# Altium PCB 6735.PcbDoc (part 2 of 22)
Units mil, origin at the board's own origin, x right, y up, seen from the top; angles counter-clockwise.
Board outline 2641.73 x 5165.35 mil, 6 copper layers (Top, Inner Layer 2, Inner Layer 3, Inner Layer 4, Inner Layer 5, Bottom), stack 35.7 mil thick; 1011 components, 790 nets, 4118 pads, 9325 vias.
Unrouted connection lines stored in the file: 4610.
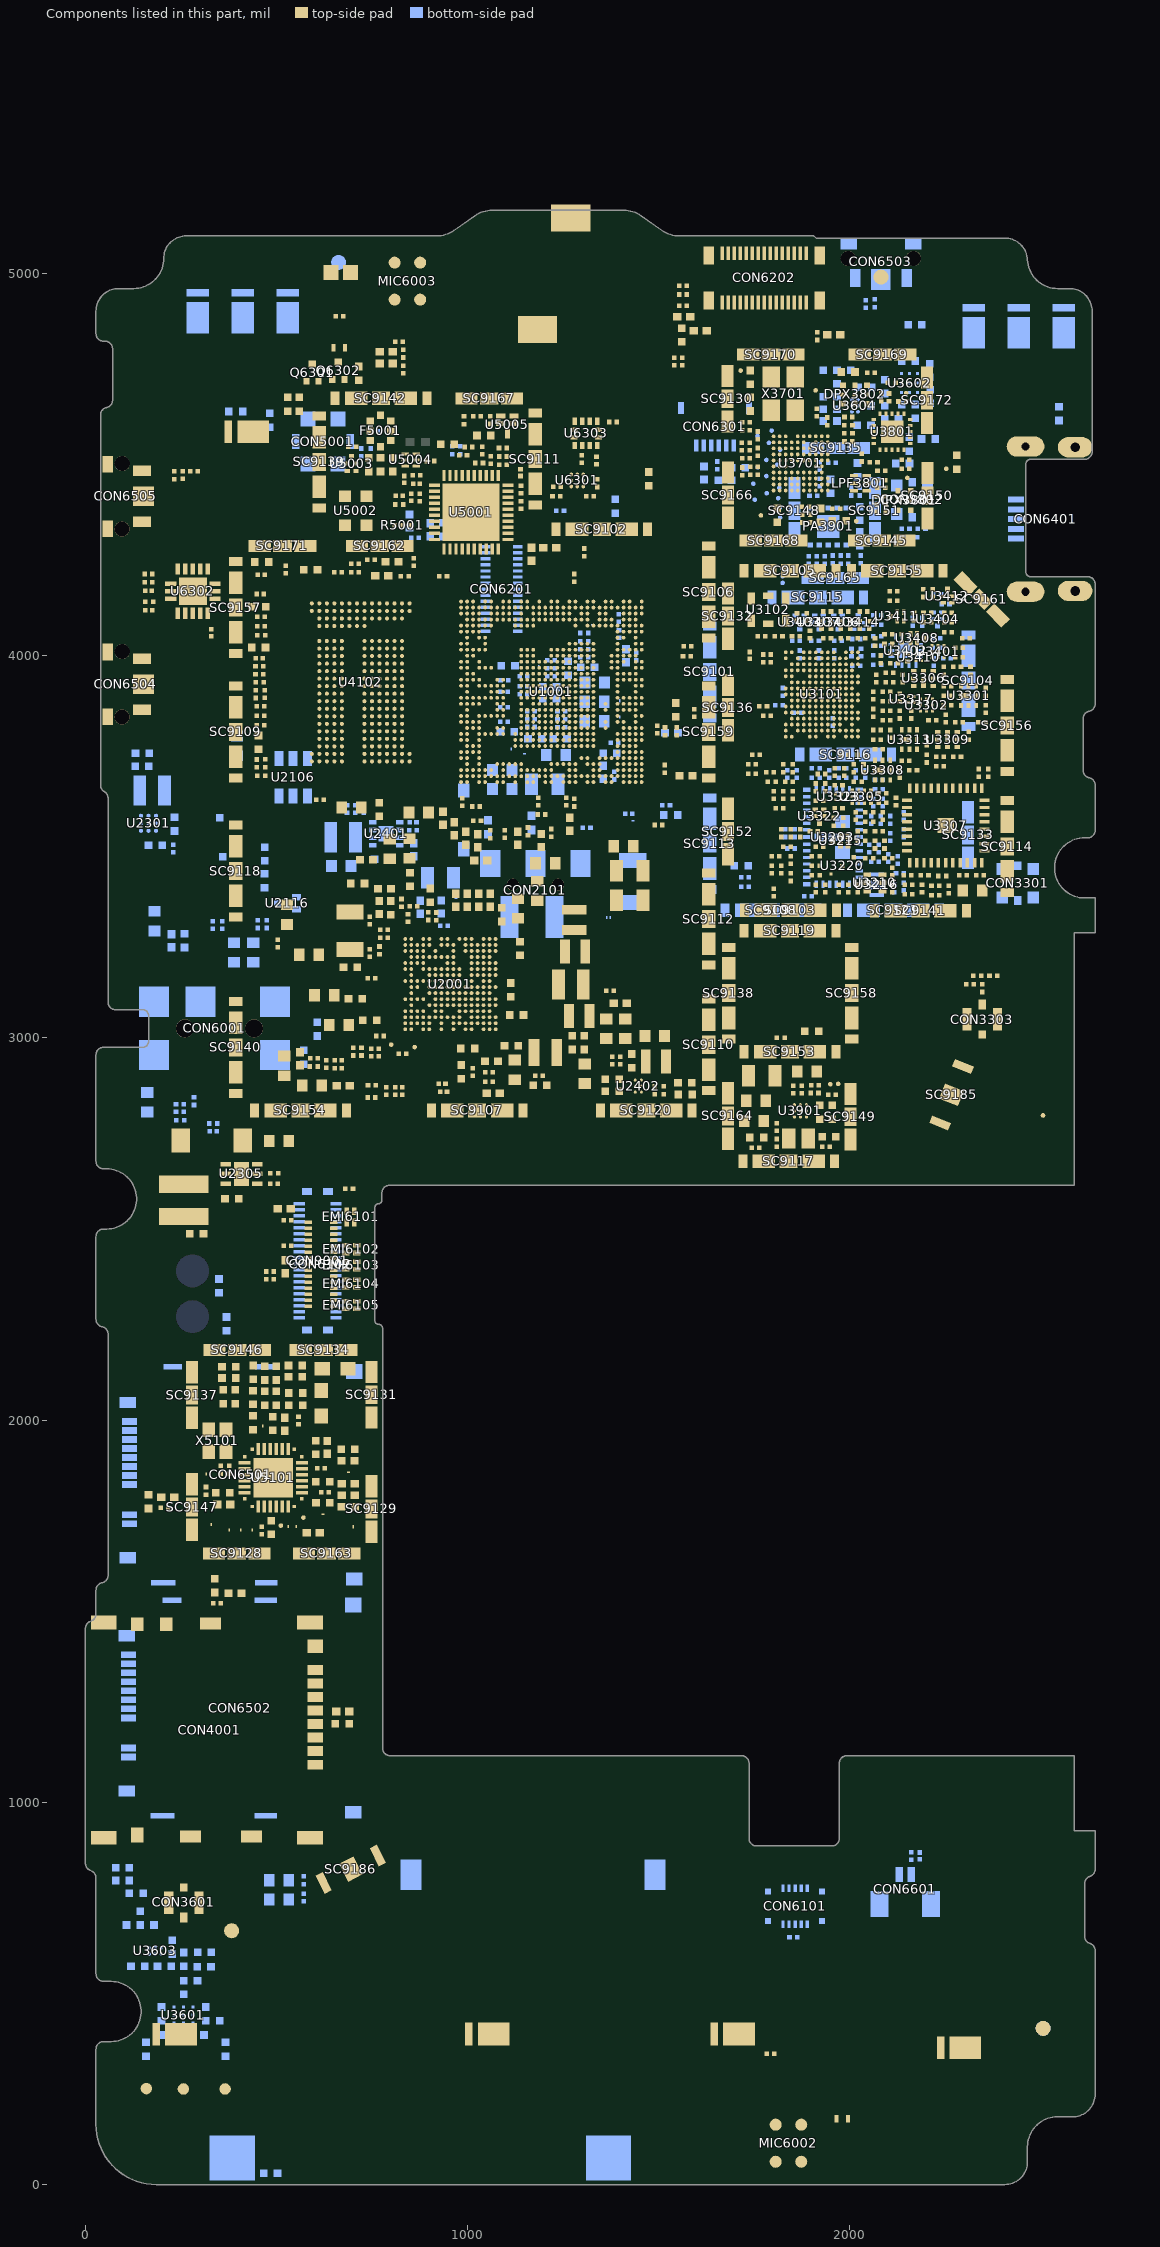
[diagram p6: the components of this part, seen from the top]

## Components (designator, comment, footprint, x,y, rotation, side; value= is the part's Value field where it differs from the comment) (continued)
C3914 "C0402" C0402 1921.08,2805.58 r90 top
C3915 "C0201" C0201 1937.31,2715.56 r0 top
C3916 "C0201" C0201 1909.08,2876.58 r0 top
C4001 "C0402" C0402 671.95,1205.49 r0 top
C4101 "C0402" C0402 452.95,4021.49 r180 top
C4102 "C0201" C0201 459.95,4053.49 r180 top
C4103 "C0402" C0402 589.08,4225.33 r180 top
C4104 "C0402" C0402 768.95,3597.49 r90 top
C4105 "C0201" C0201 660.72,4218.66 r0 top
C4106 "C0201" C0201 613.95,3623.49 r0 top
C4107 "C0201" C0201 458.95,4077.49 r180 top
C4108 "C0201" C0201 455.95,3930.49 r180 top
C4109 "C0201" C0201 704.95,4240.49 r180 top
C4110 "C0201" C0201 704.95,4218.49 r180 top
C4111 "C0402" C0402 453.31,4128.09 r180 top
C4112 "C0201" C0201 458.95,4101.49 r180 top
C4113 "C0402" C0402 461.31,4245.09 r180 top
C4114 "C0201" C0201 523.95,4225.49 r90 top
C4115 "C0201" C0201 468.95,3899.49 r90 top
C4116 "C0201" C0201 445.31,3899.39 r90 top
C5001 "C0201" C0201 820.95,4395.49 r180 top
C5002 "C0201" C0201 1139.45,4393.99 r90 top
C5003 "C0402" C0402 393.31,4639.09 r180 bottom
C5004 "C0201" C0201 698.08,4547.11 r180 top
C5005 "C0201" C0201 1139.45,4434.99 r270 top
C5006 "C0402" C0402 1042.31,4576.09 r0 top
C5007 "C0201" C0201 1060.08,4512.11 r270 top
C5008 "C0201" C0201 988.31,4524.09 r0 top
C5009 "C0201" C0201 874.08,4414.11 r90 top
C5011 "C0402" C0402 741.08,4500.11 r90 top
C5012 "C0201" C0201 866.08,4472.11 r0 top
C5013 "C0201" C0201 961.45,4317.99 r270 bottom
C5014 "C0201" C0201 971.95,4350.49 r0 bottom
C5015 "C0201" C0201 746.95,4250.83 r0 top
C5016 "C0201" C0201 1092.08,4521.11 r180 top
C5017 "C0402" C0402 804.08,4500.11 r270 top
C5101 "C0402" C0402 375.31,2110.09 r180 top
C5102 "C0402" C0402 375.31,2140.09 r180 top
C5104 "C0402" C0402 499.31,2057.09 r90 top
C5105 "C0402" C0402 469.31,2123.09 r90 top
C5106 "C0402" C0402 469.31,2057.09 r90 top
C5107 "C0402" C0402 499.31,2123.09 r90 top
C5108 "C0402" C0402 550.31,2039.09 r0 top
C5109 "C0402" C0402 549.31,2143.09 r0 top
C5110 "C0402" C0402 360.31,2061.09 r270 top
C5111 "C0402" C0402 550.31,2071.09 r180 top
C5112 "C0402" C0402 549.31,2113.09 r0 top
C5115 "C0402" C0402 490.31,1991.09 r270 top
C5116 "C0201" C0201 557.31,1999.09 r270 top
C5117 "C0402" C0402 438.31,1993.09 r270 top
C5119 "C0402" C0402 359.31,1810.09 r0 top
C5120 "C0201" C0201 315.31,1815.09 r90 top
C5121 "C0201" C0201 460.95,1711.49 r90 top
C5122 "C0402" C0402 621.3,1784.09 r0 top
C5123 "C0201" C0201 616.3,1874.09 r0 top
C5124 "C0402" C0402 602.95,1928.49 r90 top
C5125 "C0201" C0201 626.95,1811.49 r0 top
C5126 "C0402" C0402 620.95,1838.49 r0 top
C6007 "C0201" C0201 333.31,3295.65 r90 bottom
C6008 "C0201" C0201 473.81,3297.49 r90 bottom
C6012 "C0201" C0201 1792.31,342.09 r180 top
C6013 "C0201" C0201 787.31,2861.09 r270 top
C6015 "C0201" C0201 749.31,2876.09 r180 top
C6016 "C0201" C0201 748.31,2844.09 r180 top
C6019 "C0201" C0201 256.95,2816.49 r90 bottom
C6020 "C0201" C0201 247.95,2784.49 r0 bottom
C6021 "C0201" C0201 236.95,2816.49 r270 bottom
C6023 "C0201" C0201 571.31,751.09 r90 bottom
C6024 "C0201" C0201 571.31,796.09 r90 bottom
C6025 "C0201" C0201 831.31,4790.09 r270 top
C6031 "C0201" C0201 820.31,4821.09 r180 top
C6032 "C0201" C0201 831.31,4749.09 r270 top
C6034 "C0201" C0201 630.31,2932.09 r90 top
C6035 "C0201" C0201 597.68,2946.69 r180 top
C6038 "C0201" C0201 664.31,4888.09 r180 top
C6039 "C0201" C0201 597.31,2925.09 r180 top
C6101 "C0201" C0201 1851.95,647.49 r0 bottom
C6106 "C0201" C0201 528.31,2456.09 r0 top
C6107 "C0201" C0201 528.31,2523.09 r180 top
C6201 "C0201" C0201 982.95,4317.99 r90 bottom
C6202 "C0201" C0201 862.31,4309.09 r180 bottom
C6203 "C0402" C0402 1038.72,4395.31 r90 bottom
C6204 "C0402" C0402 934.95,4329.99 r270 bottom
C6205 "C0201" C0201 1563.31,4915.09 r180 top
C6206 "C0201" C0201 1914.31,4836.09 r270 top
C6207 "C0201" C0201 1563.31,4968.09 r180 top
C6210 "C0201" C0201 1563.31,4945.09 r180 top
C6303 "C0201" C0201 1338.95,4451.49 r270 top
C6304 "C0201" C0201 164.95,4191.83 r180 top
C6305 "C0201" C0201 166.95,4140.83 r180 top
C6306 "C0201" C0201 164.95,4213.83 r180 top
C6308 "C0201" C0201 1653.31,4498.09 r270 bottom
C6310 "C0402" C0402 1708.31,4492.09 r0 bottom
C6313 "C0201" C0201 1379.95,4611.49 r0 top
C6314 "C0201" C0201 1336.95,4510.49 r270 top
C6315 "C0201" C0201 1233.95,4442.49 r180 top
C6501 "C0201" C0201 206.95,1770.83 r0 top
C6502 "C0201" C0201 343.95,1520.83 r0 top
C6503 "C0201" C0201 2065.3,4922.09 r90 bottom
C6601 "C0201" C0201 2160.95,859.83 r90 bottom
C9001 "C0201" C0201 689.95,2605.49 r0 top
C10004 "C0402" C0402 1372.31,3745.09 r0 bottom
C10005 "C0201" C0201 1384.31,3772.09 r0 bottom
C10006 "C0805" C0805 1201.31,3664.09 r0 bottom
C10007 "C0402" C0402 1531.31,3583.09 r0 bottom
C10008 "C0603" C0603 1090.31,3701.09 r180 bottom
C10009 "C0603" C0603 1090.31,3651.09 r180 bottom
C10010 "C0201" C0201 1519.31,3609.09 r0 bottom
C10012 "C0603" C0603 1230.95,3740.49 r0 bottom
C10016 "C0402" C0402 1241.95,3782.49 r0 bottom
C10017 "C0402" C0402 1175.95,3782.49 r0 bottom
C10018 "C0201" C0201 1165.95,3833.49 r0 bottom
C10025 "C0201" C0201 1244.95,3854.49 r0 bottom
C10027 "C0201" C0201 1165.95,3813.49 r0 bottom
C10035 "C0201" C0201 1165.95,3854.49 r0 bottom
C10036 "C0805" C0805 1423.95,3437.49 r0 top
C10037 "C0201" C0201 1244.95,3812.49 r0 bottom
C10038 "C0805" C0805 1423.95,3360.49 r0 top
C10039 "C0201" C0201 1244.95,3833.49 r0 bottom
C10040 "C0603" C0603 1407.95,3501.49 r0 top
C10046 "C0402" C0402 1214.31,3918.09 r180 bottom
C10047 "C0402" C0402 1214.31,3888.09 r180 bottom
C10052 "C0201" C0201 1145.95,3920.49 r180 bottom
C10053 "C0201" C0201 1218.31,3988.09 r180 bottom
C10059 "C0201" C0201 1145.95,3899.49 r180 bottom
C10060 "C0201" C0201 1218.31,3946.09 r180 bottom
C10062 "C0201" C0201 1218.31,3967.09 r180 bottom
C10064 "C0201" C0201 1145.95,3946.49 r180 bottom
C10065 "C0603" C0603 1332.31,3929.59 r0 bottom
C10066 "C0603" C0603 1331.95,3879.49 r0 bottom
C10067 "C0603" C0603 1331.95,3828.49 r0 bottom
C10068 "C0201" C0201 1304.95,3995.49 r0 bottom
C10069 "C0201" C0201 1304.95,4059.49 r0 bottom
C10070 "C0201" C0201 1304.95,4037.49 r0 bottom
C10071 "C0201" C0201 1304.95,4016.49 r0 bottom
C10072 "C0201" C0201 1094.95,3865.49 r0 bottom
C10073 "C0201" C0201 1094.95,3905.49 r0 bottom
C10075 "C0402" C0402 1103.95,3801.49 r0 bottom
C10076 "C0201" C0201 1095.95,3935.49 r0 bottom
C10077 "C0201" C0201 1094.95,3827.49 r0 bottom
C10078 "C0201" C0201 1515.3,3704.09 r90 top
C10079 "C0402" C0402 1313.95,3969.49 r0 bottom
C10080 "C0402" C0402 1262.31,3967.09 r270 bottom
C10082 "C0201" C0201 835.31,4208.09 r0 top
C10083 "C0201" C0201 1441.31,3998.09 r90 bottom
C10084 "C0201" C0201 1304.95,4270.49 r90 top
C10085 "C0201" C0201 1573.31,3998.09 r0 top
C10086 "C0201" C0201 459.95,3685.49 r180 top
C10087 "C0402" C0402 1105.95,3973.49 r0 bottom
C10088 "C0201" C0201 1096.95,3533.83 r270 top
C10089 "C0201" C0201 1058.95,3532.83 r270 top
C10090 "C0201" C0201 1516.3,3802.09 r90 top
C10091 "C0201" C0201 1024.95,3567.83 r0 top
C10092 "C0201" C0201 935.95,4207.83 r0 top
C10093 "C0201" C0201 1278.95,4203.83 r90 top
C10094 "C0201" C0201 1192.95,3584.49 r180 top
C10095 "C0201" C0201 1157.95,3540.49 r90 top
C10096 "C0201" C0201 1241.95,4379.49 r0 bottom
C10097 "C0201" C0201 1574.95,4024.49 r0 top
C10098 "C0201" C0201 986.31,3617.09 r90 top
C10099 "C0201" C0201 858.95,4244.83 r90 top
C10100 "C0201" C0201 1278.95,3615.49 r270 top
CON2101 "BAT$2F$SMD$2F$KBC23S3D4XR$2F$KEIRAKU" BAT$2F$SMD$2F$KBC23S3D4XR$2F$KEIRAKU 1177.31,3401.09 r180 bottom
CON3301 "MM8130-2602" MM8130-2602 2439.31,3405.09 r180 bottom
CON3303 "COAXIAL$2F$SMD$2F$TA-RF02-001-03-811" COAXIAL$2F$SMD$2F$TA-RF02-001-03-811 2346.3,3049.09 r180 top
CON3601 "COAXIAL$2F$SMD$2F$TA-RF02-001-03-811" COAXIAL$2F$SMD$2F$TA-RF02-001-03-811 257.31,737.09 r0 top
CON3802 "MM8130-2602" MM8130-2602 2162.95,4407.83 r0 bottom
CON4001 "MICROSD$2F$8P$2F$SMD$2F$TA-M017-012-07-811" MICROSD$2F$8P$2F$SMD$2F$TA-M017-012-07-811 620.87,1098.5 r270 top
CON5001 "MM8430-2600B" MM8430-2600B 621.3,4560.09 r270 bottom
CON6001 "AUDIOJACK$2F$5P$2F$SMD$2F$EJ-3699M-GP" AUDIOJACK$2F$5P$2F$SMD$2F$EJ-3699M-GP 179.31,3094.59 r180 bottom
CON6101 "CON5X2$2F$SMD$2F$P0.4$2F$F$2F$AXE510127" CON5X2$2F$SMD$2F$P0.4$2F$F$2F$AXE510127 1856.5,727.94 r0 bottom
CON6102 "CON15X2$2F$SMD$2F$F$2F$P0.4$2F$24-5804-030-000-829HT" CON15X2$2F$SMD$2F$F$2F$P0.4$2F$24-5804-030-000-829HT 616.08,2407.99 r270 top
CON6201 "CAMERA_MODULE$2F$30P$2F$SMD$2F$CM9156-B1300BA-E" CAMERA_MODULE$2F$30P$2F$SMD$2F$CM9156-B1300BA-E 1088.95,4174.4 r270 bottom
CON6202 "CAMERA_MODULE$2F$30P$2F$SMD$2F$Q5V22K-0JG" CAMERA_MODULE$2F$30P$2F$SMD$2F$Q5V22K-0JG 1775.95,4988.49 r0 top
CON6301 "H6$2F$SMD$2F$P0.5$2F$FH34S-06S-0.5SH" H6$2F$SMD$2F$P0.5$2F$FH34S-06S-0.5SH 1647.08,4550.11 r0 bottom
CON6401 "MICROUSB$2F$5P$2F$SMD$2F$P0.65$2F$R$2F$KIU90511S1R" MICROUSB$2F$5P$2F$SMD$2F$P0.65$2F$R$2F$KIU90511S1R 2434.95,4357.49 r270 bottom
CON6501 "SIM$2F$10P$2F$SMD$2F$SCGD1B0307" SIM$2F$10P$2F$SMD$2F$SCGD1B0307 115.3,1857.09 r270 bottom
CON6502 "SIM$2F$10P$2F$SMD$2F$SCGD1B0307" SIM$2F$10P$2F$SMD$2F$SCGD1B0307 113.14,1246.78 r270 bottom
CON6503 "CITIZENLS10_BOSS" CITIZENLS10_BOSS 2081.3,5039.09 r90 bottom
CON6504 "CITIZENLS10_BOSS" CITIZENLS10_BOSS 96.3,3925.09 r180 top
CON6505 "CITIZENLS10_BOSS" CITIZENLS10_BOSS 96.3,4416.83 r180 top
CON6601 "H2$2F$SMD$2F$P0.8$2F$SM02B-SURS-TF$2F$SUR" H2$2F$SMD$2F$P0.8$2F$SM02B-SURS-TF$2F$SUR 2144.95,810.83 r180 bottom
CON9001 "CON20X2$2F$SMD$2F$M$2F$AXT640124$2F$FPC" CON20X2$2F$SMD$2F$M$2F$AXT640124$2F$FPC 607.3,2417.09 r270 bottom
D2103 "DIODE$2F$SMD$2F$MMSZ5221B" DIODE$2F$SMD$2F$MMSZ5221B 989.95,3570.49 r90 bottom
D2301 "RB160M-30-EVB" RB160M-30-EVB 330.31,2731.15 r0 top
D6301 "LED190" LED190 668.37,5002.92 r180 top
DIPX3801 "DIPLEXER$2F$6P$2F$SMD$2F$FI212P0829G2" DIPLEXER$2F$6P$2F$SMD$2F$FI212P0829G2 2142.33,4406.09 r90 top
DPX3802 "SAW$2F$8P$2F$SMD$2F$D2.0X1.6$2F$SAYFH833MCA0F00" SAW$2F$8P$2F$SMD$2F$D2.0X1.6$2F$SAYFH833MCA0F00 2012.95,4683.49 r0 top
EMI6101 "L$2F$CHOKE$2F$SMD$2F$DLP0NS0806" L$2F$CHOKE$2F$SMD$2F$DLP0NS0806 693.95,2531.83 r270 top
EMI6102 "L$2F$CHOKE$2F$SMD$2F$DLP0NS0806" L$2F$CHOKE$2F$SMD$2F$DLP0NS0806 695.3,2447.09 r180 top
EMI6103 "L$2F$CHOKE$2F$SMD$2F$DLP0NS0806" L$2F$CHOKE$2F$SMD$2F$DLP0NS0806 695.3,2405.09 r180 top
EMI6104 "L$2F$CHOKE$2F$SMD$2F$DLP0NS0806" L$2F$CHOKE$2F$SMD$2F$DLP0NS0806 695.3,2357.09 r180 top
EMI6105 "L$2F$CHOKE$2F$SMD$2F$DLP0NS0806" L$2F$CHOKE$2F$SMD$2F$DLP0NS0806 695.3,2301.09 r180 top
F5001 "FILTER$2F$SMD$2F$LFD211G57ME3" FILTER$2F$SMD$2F$LFD211G57ME3 771.95,4588.11 r270 top
FM9101 "FD" FD 2081.45,4990.49 r0 top
FM9102 "FD" FD 662.31,5029.09 r180 bottom
FM9103 "FD" FD 2505.77,408.68 r180 bottom
FM9104 "FD" FD 2505.77,408.68 r0 top
FM9105 "FD" FD 382.57,663.99 r0 top
L2001 "L$2F$IND$2F$SMD$2F$2520" L$2F$IND$2F$SMD$2F$2520 1269.95,3139.83 r0 top
L2003 "L$2F$IND$2F$SMD$2F$VLS201610E" L$2F$IND$2F$SMD$2F$VLS201610E 1291.95,3057.49 r0 top
L2006 "L$2F$IND$2F$SMD$2F$VLS201610E" L$2F$IND$2F$SMD$2F$VLS201610E 1280.95,3225.83 r0 top
L2008 "L$2F$IND$2F$SMD$2F$VLS201610E" L$2F$IND$2F$SMD$2F$VLS201610E 1278.92,3308.61 r90 top
L2009 "L$2F$IND$2F$SMD$2F$2016" L$2F$IND$2F$SMD$2F$2016 1203.11,2961.89 r0 top
L2401 "L$2F$IND$2F$SMD$2F$2520" L$2F$IND$2F$SMD$2F$2520 674.2,3525.11 r180 bottom
L2402 "L$2F$IND$2F$SMD$2F$VLS201610E" L$2F$IND$2F$SMD$2F$VLS201610E 1492.31,2938.09 r180 top
L3206 "L0201" L0201 2085.65,3615.59 r270 bottom
L3207 "L0201" L0201 2075.65,3675.59 r180 bottom
L3209 "L0201" L0201 2140.65,3535.59 r90 bottom
L3210 "L0201" L0201 1910.65,3475.59 r0 top
L3211 "L0201" L0201 1995.65,3390.59 r90 top
L3213 "L0201" L0201 1910.65,3390.59 r90 top
L3214 "L0201" L0201 2100.65,3470.59 r90 bottom
L3215 "L0201" L0201 1850.65,3635.59 r90 top
L3217 "L0201" L0201 1910.65,3680.59 r0 bottom
L3218 "L0201" L0201 2050.65,3470.59 r180 top
L3219 "L0201" L0201 2090.65,3505.59 r90 top
L3221 "L0201" L0201 2030.65,3515.59 r180 top
L3222 "L0201" L0201 2050.65,3565.59 r180 top
L3223 "L0201" L0201 2115.65,3390.59 r90 bottom
L3234 "L0201" L0201 2130.65,3430.59 r180 bottom
L3238 "L0201" L0201 1795.65,3440.59 r90 top
L3301 "C0201" C0201 2345.65,3825.59 r180 top
L3302 "L0201" L0201 2255.65,3870.59 r0 top
L3303 "L0201" L0201 2355.65,3905.59 r90 top
L3304 "L0201" L0201 2255.65,3920.59 r180 top
L3305 "L0201" L0201 2130.65,3890.59 r270 top
L3308 "L0201" L0201 2068.65,3940.59 r90 top
L3309 "L0201" L0201 2280.65,3970.59 r180 top
L3310 "L0201" L0201 2138.65,3940.59 r90 top
L3311 "L0201" L0201 2245.65,3960.59 r270 top
L3312 "L0201" L0201 2070.65,3805.59 r0 top
L3313 "L0201" L0201 2250.65,3835.59 r270 top
L3314 "L0201" L0201 2310.65,3790.59 r270 top
L3315 "L0201" L0201 2130.65,3690.59 r270 top
L3316 "L0201" L0201 2075.65,3755.59 r0 top
L3317 "L0201" L0201 2314.3,3140.09 r180 top
L3318 "L0201" L0201 2165.65,3700.59 r0 top
L3322 "L0201" L0201 2336.65,3693.59 r90 top
L3328 "L0201" L0201 2130.65,3845.59 r90 top
L3329 "L0201" L0201 2060.65,3850.59 r90 top
L3330 "L0201" L0201 2200.65,3775.59 r90 top
L3331 "L0201" L0201 1905.65,3540.59 r0 top
L3332 "L0201" L0201 2015.65,3580.59 r90 top
L3333 "L0201" L0201 1920.65,3620.59 r0 top
L3334 "L0201" L0201 1925.65,3690.59 r0 top
L3335 "L0201" L0201 2060.65,3895.59 r270 top
L3336 "L0201" L0201 2030.65,3740.59 r180 top
L3337 "L0201" L0201 2020.65,3670.59 r180 top
L3338 "L0201" L0201 2085.65,3640.59 r0 top
L3340 "L0201" L0201 2085.65,3580.59 r90 top
L3341 "L0201" L0201 1985.65,3740.59 r180 top
L3342 "L0201" L0201 2120.65,3618.59 r90 top
L3343 "L0201" L0201 1970.65,3660.59 r180 top
L3344 "L0201" L0201 1958.15,3565.59 r270 top
L3346 "L0201" L0201 2375.3,3163.09 r0 top
L3347 "L0201" L0201 2280.65,3735.59 r0 top
L3350 "L0201" L0201 1970.65,3600.59 r180 top
L3351 "L0201" L0201 2315.65,3960.59 r270 top
L3401 "L0201" L0201 1940.65,4115.59 r0 top
L3402 "L0201" L0201 2226.65,4046.09 r0 bottom
L3403 "L0201" L0201 1940.65,4045.59 r0 top
L3409 "L0201" L0201 2030.65,4045.59 r0 top
L3410 "L0201" L0201 2035.65,4115.59 r0 top
L3411 "L0201" L0201 1909.15,4038.59 r0 bottom
L3412 "L0201" L0201 1985.65,4115.59 r0 top
L3413 "L0201" L0201 1985.65,4045.59 r0 top
L3414 "L0201" L0201 1969.15,4038.59 r180 bottom
L3415 "L0201" L0201 2189.15,4088.59 r270 bottom
L3416 "L0201" L0201 2065.65,4035.59 r90 top
L3417 "L0201" L0201 2135.65,4045.59 r270 top
L3418 "L0201" L0201 2216.65,4163.59 r270 top
L3421 "L0201" L0201 1859.15,4038.59 r180 bottom
L3429 "L0201" L0201 2167.65,4102.59 r90 top
L3430 "L0201" L0201 2114.15,4143.59 r180 top
L3431 "L0201" L0201 2256.65,4112.59 r0 top
L3433 "C0201" C0201 2071.65,4081.09 r0 bottom
L3437 "L0201" L0201 2202.65,4087.59 r0 top
L3439 "L0201" L0201 2080.65,3990.59 r90 top
L3440 "L0201" L0201 2150.65,3995.59 r90 top
L3441 "L0201" L0201 2256.65,4061.59 r180 top
L3442 "L0201" L0201 2250.57,4135.24 r180 bottom
L3443 "L0201" L0201 1869.15,4003.59 r90 bottom
L3444 "L0201" L0201 2016.65,3973.59 r180 bottom
L3445 "L0201" L0201 2016.65,4043.59 r180 bottom
L3499 "L0201" L0201 2219.15,3983.59 r270 bottom
L3601 "L0402" L0402 292.3,391.09 r0 bottom
L3602 "L0402" L0402 2210.3,4678.09 r270 bottom
L3603 "L0402" L0402 158.3,354.09 r90 bottom
L3605 "L0402" L0402 310.31,570.09 r0 bottom
L3606 "L0402" L0402 314.95,446.49 r270 bottom
L3607 "L0402" L0402 2205.29,4567.09 r0 bottom
L3608 "L0402" L0402 2153.3,4771.09 r0 bottom
L3609 "L0402" L0402 206.31,571.09 r180 bottom
L3610 "L0402" L0402 137.31,571.09 r0 bottom
L3611 "L0402" L0402 2073.3,4654.09 r180 bottom
L3612 "L0402" L0402 2037.31,4603.09 r180 bottom
L3801 "L0201" L0201 2145.95,4331.83 r180 bottom
L3802 "L0201" L0201 2187.95,4331.83 r0 bottom
L3803 "L0201" L0201 2094.33,4386.09 r90 top
L3804 "L0201" L0201 2080.33,4417.09 r0 top
L3805 "L0201" L0201 2092.33,4449.09 r270 top
L3806 "L0201" L0201 2062.31,4506.09 r180 top
L3815 "L0201" L0201 1921.31,4453.09 r270 bottom
L3816 "L0402" L0402 1995.31,4742.09 r180 top
L3819 "L0201" L0201 1995.95,4624.49 r0 top
L3820 "L0201" L0201 1995.95,4560.49 r0 top
L3821 "L0201" L0201 2109.31,4714.09 r0 top
L3822 "L0201" L0201 1953.31,4505.09 r0 bottom
L3901 "L0201" L0201 1986.08,4241.11 r0 bottom
L5002 "L0402" L0402 947.31,4553.09 r180 top
L5003 "L0402" L0402 772.08,4500.11 r90 top
L5004 "L0402" L0402 482.31,4616.09 r90 bottom
L5005 "L0201" L0201 1092.08,4500.11 r0 top
L5006 "L0201" L0201 1091.95,4543.49 r180 top
L5007 "L0201" L0201 1059.08,4616.11 r270 top
L5008 "L0201" L0201 990.31,4616.09 r270 top
L5009 "L0201" L0201 1002.31,4546.09 r180 top
L5010 "L0201" L0201 1030.08,4504.11 r180 top
L5011 "L0201" L0201 721.31,4532.09 r270 bottom
L5012 "L0201" L0201 756.31,4587.09 r0 bottom
L5101 "L$2F$IND$2F$SMD$2F$0603" L$2F$IND$2F$SMD$2F$0603 617.31,2044.09 r90 top
L5102 "L$2F$IND$2F$SMD$2F$0603" L$2F$IND$2F$SMD$2F$0603 653.31,2134.09 r180 top
L6001 "SB$2F$0402" SB$2F$0402 224.95,3254.49 r90 bottom
L6002 "BEAD0603" BEAD0603 180.95,3305.49 r270 bottom
LED2302 "FLASH_LED$2F$LUW_F8DN" FLASH_LED$2F$LUW_F8DN 354.95,3536.49 r180 bottom
LPF3801 "FILTER$2F$SMD$2F$FI-168L083523-T" FILTER$2F$SMD$2F$FI-168L083523-T 2027.31,4451.09 r270 top
MIC6002 "FILTER$2F$SMD$2F$SPU0410HR5H-PB" FILTER$2F$SMD$2F$SPU0410HR5H-PB 1839.31,108.09 r180 top
MIC6003 "FILTER$2F$SMD$2F$SPU0410HR5H-PB" FILTER$2F$SMD$2F$SPU0410HR5H-PB 842.31,4980.09 r0 top
NTC3701 "R0402" R0402 2020.08,4486.11 r90 bottom
NTC6301 "R0402" R0402 1473.95,4462.49 r90 top
NTC6302 "R0201" R0201 1860.65,3690.59 r90 bottom
PA3901 "RF7255" RF7255 1943.31,4338.11 r90 bottom
PL2303 "L$2F$CHOKE$2F$SMD$2F$LQH3NP" L$2F$CHOKE$2F$SMD$2F$LQH3NP 257.31,2575.09 r90 top
PL2305 "L$2F$IND$2F$SMD$2F$2520" L$2F$IND$2F$SMD$2F$2520 174.31,3647.09 r0 bottom
PL3901 "L$2F$IND$2F$SMD$2F$LQM21PNR54MG0" L$2F$IND$2F$SMD$2F$LQM21PNR54MG0 1865.31,2736.56 r270 top
Q6301 "VMT3$2F$SMD$2F$RUM003N02" VMT3$2F$SMD$2F$RUM003N02 593.95,4740.49 r0 top
Q6302 "VMT3$2F$SMD$2F$RUM003N02" VMT3$2F$SMD$2F$RUM003N02 661.45,4745.49 r0 top
R1004 "SB$2F$0402" SB$2F$0402 1571.31,3686.09 r0 top
R1005 "R0603" R0603 871.95,3589.49 r180 top
R1007 "R0201" R0201 1372.31,3123.09 r0 top
R1008 "SB$2F$0402" SB$2F$0402 775.31,4209.09 r180 top
R1009 "SB$2F$0402" SB$2F$0402 1414.31,4000 r90 bottom
R1011 "R0201" R0201 1399.31,2941.09 r90 top
R1012 "SB$2F$0402" SB$2F$0402 1214.95,4282.83 r180 top
R1013 "SB$2F$0402" SB$2F$0402 1399.31,3091.09 r0 top
R1014 "SB$2F$0402" SB$2F$0402 935.31,3575.09 r270 top
R1016 "SB$2F$0402" SB$2F$0402 995.31,3522.09 r270 top
R1018 "SB$2F$0402" SB$2F$0402 965.31,3547.09 r270 top
R1021 "R0603" R0603 695.95,3602.49 r0 top
R1022 "SB$2F$0402" SB$2F$0402 1025.95,3515.49 r270 top
R1023 "SB$2F$0402" SB$2F$0402 1034.31,3464.09 r180 top
R1026 "SB$2F$0402" SB$2F$0402 1166.95,4265.49 r90 top
R1027 "SB$2F$0402" SB$2F$0402 1354.31,3695.09 r270 bottom
R1028 "SB$2F$0402" SB$2F$0402 1192.95,3516.49 r270 top
R1029 "SB$2F$0402" SB$2F$0402 1267.31,3559.09 r270 top
R1030 "SB$2F$0402" SB$2F$0402 1130.95,3522.49 r90 top
R1031 "SB$2F$0402" SB$2F$0402 801.95,4245.83 r180 top
R1035 "SB$2F$0402" SB$2F$0402 1533.31,3798.09 r0 bottom
R1036 "SB$2F$0201" SB$2F$0201 1421.31,3586.09 r180 bottom
R1037 "NC$2F$MMD$2F$L1$2F$4MIL" NC$2F$MMD$2F$L1$2F$4MIL 1432.31,3568.09 r180 bottom
R1101 "R0201" R0201 1021.95,3605.49 r180 top
R1102 "SB$2F$0201" SB$2F$0201 1738.15,4000.59 r90 top
R1103 "R0201" R0201 457.95,3867.49 r0 top
R1105 "R0201" R0201 470.13,3718.54 r90 top
R1106 "R0201" R0201 457.81,3843.33 r180 top
R1109 "R0201" R0201 1499.31,3557.09 r0 top
R1201 "R0201" R0201 1257.95,3618.49 r270 top
R1202 "R0201" R0201 1550.95,4779.83 r180 top
R1203 "R0201" R0201 1550.95,4759.83 r180 top
R1204 "R0201" R0201 482.6,2368.89 r180 top
R1205 "R0201" R0201 482.6,2388.89 r180 top
R1206 "R0201" R0201 1297.95,4514.49 r90 top
R1207 "R0201" R0201 1231.95,4417.49 r0 top
R1208 "R0201" R0201 1394.95,4098.49 r270 bottom
R1209 "R0201" R0201 1395.95,4056.49 r90 bottom
R1227 "R0201" R0201 1184.95,3618.83 r270 top
R2002 "R0201" R0201 1218.95,3536.49 r270 top
R2003 "R0201" R0201 843.95,3313.49 r270 top
R2005 "R0201" R0201 1055.81,2885.65 r0 top
R2026 "R0201" R0201 503.31,3247.09 r90 top
R2030 "R0201" R0201 769.31,3229.09 r90 top
R2032 "R0402" R0402 469.31,3481.09 r90 bottom
R2033 "R0402" R0402 798.31,3340.09 r90 top
R2034 "R0201" R0201 1311.31,3550.09 r180 bottom
R2036 "SB$2F$0603" SB$2F$0603 847.95,3495.49 r270 top
R2037 "SB$2F$0603" SB$2F$0603 624.95,3111.83 r0 top
R2039 "SB$2F$0402" SB$2F$0402 968.95,3359.83 r270 top
R2040 "SB$2F$0402" SB$2F$0402 1058.95,3359.83 r270 top
R2041 "SB$2F$0402" SB$2F$0402 1028.95,3359.83 r270 top
R2042 "SB$2F$0402" SB$2F$0402 768.31,3341.09 r270 top
R2043 "SB$2F$0402" SB$2F$0402 930.95,3342.49 r270 bottom
R2044 "SB$2F$0402" SB$2F$0402 875.95,3341.49 r270 bottom
R2045 "SB$2F$0402" SB$2F$0402 735.31,3466.09 r0 top
R2046 "SB$2F$0402" SB$2F$0402 998.95,3359.83 r270 top
R2047 "SB$2F$0603" SB$2F$0603 796.31,3494.09 r270 top
R2048 "SB$2F$0402" SB$2F$0402 1062.31,2938.76 r0 top
R2098 "SB$2F$0603" SB$2F$0603 663.31,3033.83 r0 top
R2099 "SB$2F$0603" SB$2F$0603 584.95,3217.83 r0 top
R2103 "R0402" R0402 711.95,3403.83 r180 top
R2105 "SB$2F$0402" SB$2F$0402 782.31,3390.09 r0 top
R2135 "R0805" R0805 928.95,3419.49 r0 bottom
R2137 "R1206" R1206 1431.95,3409.49 r270 bottom
R2138 "NC$2F$MMD$2F$L1$2F$4MIL" NC$2F$MMD$2F$L1$2F$4MIL 1373.31,3315.09 r90 bottom
R2139 "NC$2F$MMD$2F$L1$2F$4MIL" NC$2F$MMD$2F$L1$2F$4MIL 1363.31,3315.09 r90 bottom
R2140 "NC$2F$MMD$2F$L1$2F$4MIL" NC$2F$MMD$2F$L1$2F$4MIL 969.95,3365.49 r0 bottom
R2192 "R0402" R0402 468.31,3411.09 r270 bottom
R2308 "R0402" R0402 290.95,2487.83 r0 top
R2310 "R0201" R0201 492.95,2618.49 r0 top
R2316 "R0402" R0402 148.95,3744.49 r0 bottom
R2320 "R0402" R0402 182.95,3504.49 r0 bottom
R2403 "SB$2F$0201" SB$2F$0201 857.2,3564.11 r180 bottom
R2404 "R0201" R0201 1378.31,2941.09 r270 top
R2405 "R0402" R0402 1378.31,2892.09 r0 top
R2406 "R0201" R0201 857.2,3543.11 r180 bottom
R2407 "R0201" R0201 1489.31,2863.09 r90 top
R2408 "SB$2F$0402" SB$2F$0402 859.31,3492.09 r270 bottom
R2416 "R0201" R0201 705.8,3599.2 r90 bottom
R2417 "R0201" R0201 728.31,3599.09 r270 bottom
R3101 "R0201" R0201 1743.65,3716.09 r180 top
R3102 "R0201" R0201 1754.15,3741.09 r180 top
R3103 "R0201" R0201 1743.65,3691.09 r0 top
R3105 "R0201" R0201 1773.15,3868.09 r180 top
R3107 "R0201" R0201 1768.65,4050.59 r180 top
R3108 "R0201" R0201 1886.65,4101.09 r90 top
R3201 "R0201" R0201 1845.65,3420.59 r270 top
R3209 "R0201" R0201 1725.65,3420.59 r180 bottom
R3210 "R0201" R0201 1725.65,3395.59 r180 bottom
R3214 "R0201" R0201 1800.65,3635.59 r90 top
R3220 "R0402" R0402 1900.31,3017.56 r180 top
R3224 "R0402" R0402 1568.31,2883.09 r180 top
R3226 "R0201" R0201 1795.65,3670.59 r180 top
R3230 "R0201" R0201 1845.65,3465.59 r270 top
R3231 "R0201" R0201 1835.65,3500.59 r180 top
R3232 "R0201" R0201 1835.65,3690.59 r270 bottom
R3234 "R0402" R0402 1569.31,2852.09 r180 top
R3239 "R0805" R0805 1769.08,2900.58 r180 top
R3278 "R0402" R0402 1715.65,3450.59 r0 bottom
R3301 "R0201" R0201 2223.65,3373.59 r0 top
R3302 "R0201" R0201 2223.65,3398.59 r180 top
R3305 "R0201" R0201 2346.3,3130.09 r270 top
R3306 "R0201" R0201 2188.65,3390.59 r270 top
R3327 "R0201" R0201 2153.65,3375.59 r0 top
R3328 "R0201" R0201 2150.65,3425.59 r180 top
R3333 "R0201" R0201 2195.65,3425.59 r180 top
R3334 "R0201" R0201 2153.65,3400.59 r180 top
R3380 "R0402" R0402 1189.15,2876.09 r0 top
R3601 "R0402" R0402 366.3,354.09 r90 bottom
R3602 "R0402" R0402 198.95,446.49 r270 bottom
R3603 "R0402" R0402 257.31,589.09 r270 bottom
R3604 "R0402" R0402 2155.3,4553.09 r90 bottom
R3605 "R0402" R0402 2170.3,4866.09 r180 bottom
R3606 "R0402" R0402 2153.3,4657.09 r0 bottom
R3607 "R0402" R0402 216.3,391.09 r180 bottom
R3608 "R0402" R0402 332.95,428.49 r0 bottom
R3609 "R0402" R0402 274.95,533.49 r180 bottom
R3610 "R0402" R0402 256.95,515.49 r270 bottom
R3611 "R0402" R0402 2171.3,4639.09 r270 bottom
R3612 "R0402" R0402 2109.3,4620.09 r180 bottom
R3613 "R0402" R0402 143.3,697.09 r270 bottom
R3614 "R0402" R0402 2209.3,4746.09 r90 bottom
R3615 "R0402" R0402 2091.3,4704.09 r90 bottom
R3616 "R0402" R0402 1948.3,4747.09 r0 bottom
R3617 "R0402" R0402 96.95,828.49 r180 bottom
R3618 "R0402" R0402 484.3,29.09 r0 bottom
R3619 "R0402" R0402 1948.3,4645.09 r180 bottom
R3622 "R0402" R0402 2546.95,4633.49 r270 bottom
R3624 "R0402" R0402 125.3,679.09 r180 bottom
R3625 "R0402" R0402 161.3,679.09 r0 bottom
R3626 "R0402" R0402 132.95,762.49 r0 bottom
R3627 "R0402" R0402 96.95,795.49 r180 bottom
R3628 "R0402" R0402 1984.3,4747.09 r0 bottom
R3629 "R0402" R0402 1966.3,4729.09 r270 bottom
R3630 "R0402" R0402 1948.3,4677.09 r0 bottom
R3631 "R0402" R0402 1948.3,4614.09 r180 bottom
R3701 "R0201" R0201 1875.5,4358.42 r270 top
R3702 "R0201" R0201 1896.5,4358.42 r90 top
R3703 "R0201" R0201 1883.95,4389.49 r0 top
R3704 "R0201" R0201 1912.95,4636.49 r90 top
R3709 "R0402" R0402 2279.31,4506.09 r90 top
R3712 "R0201" R0201 1737.95,4547.49 r90 top
R3713 "R0402" R0402 1972.3,4353.09 r180 top
R3714 "R0201" R0201 1727.95,4610.49 r0 top
R3715 "R0402" R0402 1739.31,4728.09 r270 top
R3716 "R0201" R0201 1716.95,4547.49 r270 top
R3717 "R0201" R0201 1727.95,4516.49 r180 top
R3718 "R0201" R0201 1727.95,4589.49 r180 top
R3719 "R0201" R0201 1717.95,4482.49 r90 top
R3732 "R0201" R0201 1758.95,4533.49 r90 top
R3801 "R0201" R0201 2070.33,4386.09 r90 top
R3802 "R0201" R0201 2071.33,4449.09 r90 top
R3804 "R0201" R0201 2082.33,4484.09 r180 top
R3813 "R0201" R0201 2055.31,4740.09 r180 top
R3815 "R0201" R0201 2102.31,4676.09 r90 top
R3817 "R0201" R0201 1921.31,4496.09 r270 bottom
R3818 "R0201" R0201 2031.45,4517.99 r270 top
R3819 "R0201" R0201 2082.31,4676.09 r90 top
R3901 "R0603" R0603 1754.08,2835.58 r180 top
R3902 "R0201" R0201 1955.08,4252.11 r90 bottom
R3903 "R0201" R0201 1904.31,4418.09 r180 bottom
R3904 "R0201" R0201 1953.31,2851.56 r0 top
R3905 "R0402" R0402 1954.08,2805.58 r270 top
R3906 "R0402" R0402 1945.31,2741.56 r0 top
R3907 "R0201" R0201 1873.95,2864.96 r270 top
R3908 "R0201" R0201 1907.95,2855.96 r180 top
R3909 "R0603" R0603 1749.08,2782.58 r0 top
R3910 "R0201" R0201 1808.31,2725.56 r270 top
R3911 "R0201" R0201 1753.08,2712.58 r0 top
R4001 "SB$2F$0402" SB$2F$0402 672.95,1237.49 r0 top
R4101 "SB$2F$0201" SB$2F$0201 456.95,4161.49 r180 top
R4102 "SB$2F$0201" SB$2F$0201 460.31,4212.09 r180 top
R4103 "R0201" R0201 454.95,3951.49 r0 top
R4104 "R0201" R0201 454.95,3972.49 r0 top
R5001 "R0201_1-2" R0201_1-2 829.08,4341.11 r0 top
R5003 "SB$2F$0201" SB$2F$0201 820.95,4418.49 r0 top
R5004 "R0402" R0402 430.31,4598.09 r0 bottom
R5005 "R0201" R0201 746.31,4552.09 r90 bottom
R5006 "R0201" R0201 970.06,4527.5 r0 bottom
R5007 "R0201" R0201 902.95,4509.49 r0 top
R5008 "SB$2F$0201" SB$2F$0201 866.08,4450.11 r180 top
R5013 "R0201" R0201 970.06,4547.5 r0 bottom
R5014 "R0201" R0201 1024.31,4626.09 r0 top
R5015 "SB$2F$0201" SB$2F$0201 834.08,4461.11 r270 top
R5016 "R0201" R0201 1038.31,4537.09 r270 top
R5101 "R0402" R0402 368.95,2251.83 r270 bottom
R5102 "R0402" R0402 349.31,2351.09 r270 bottom
R5103 "R0402" R0402 438.31,2059.09 r270 top
R5104 "R0402" R0402 439.31,2125.09 r90 top
R5105 "R0402" R0402 392.31,2061.09 r90 top
R5108 "R0201" R0201 354.31,1870.09 r90 top
R5116 "R0402" R0402 486.3,1719.09 r90 top
R5128 "R0402" R0402 686.95,1923.49 r0 top
R5129 "R0402" R0402 687.95,1773.49 r0 top
R5130 "R0201" R0201 376.31,1870.09 r270 top
R6002 "R0402" R0402 606.31,3023.09 r270 bottom
R6003 "SB$2F$0402" SB$2F$0402 561.31,2945.09 r90 top
R6004 "SB$2F$0402" SB$2F$0402 673.95,2874.83 r180 top
R6005 "R0402" R0402 570.95,2949.49 r270 bottom
R6006 "R0201" R0201 451.31,3297.49 r90 bottom
R6007 "R0201" R0201 358.31,3295.65 r90 bottom
R6011 "R0201" R0201 334.31,2776.09 r0 bottom
R6012 "R0402" R0402 258.95,3254.49 r90 bottom
R6019 "SB$2F$0603" SB$2F$0603 506.31,796.09 r180 bottom
R6020 "SB$2F$0603" SB$2F$0603 506.31,746.09 r180 bottom
R6021 "SB$2F$0402" SB$2F$0402 786.95,4764.49 r0 top
R6022 "SB$2F$0402" SB$2F$0402 786.95,4795.49 r0 top
R6023 "SB$2F$0201" SB$2F$0201 819.31,2851.09 r0 top
R6024 "SB$2F$0201" SB$2F$0201 819.31,2871.09 r0 top
R6025 "SB$2F$0201" SB$2F$0201 661.31,2942.09 r0 top
R6026 "SB$2F$0201" SB$2F$0201 661.31,2921.09 r0 top
R6027 "SB$2F$0201" SB$2F$0201 932.95,2880.49 r180 top
R6028 "SB$2F$0201" SB$2F$0201 936.95,2859.49 r180 top
R6029 "R0201" R0201 283.95,2834.49 r90 bottom
R6030 "SB$2F$0201" SB$2F$0201 334.31,2756.09 r180 bottom
R6104 "SB$2F$0402" SB$2F$0402 522.31,2401.09 r270 top
R6105 "SB$2F$0402" SB$2F$0402 520.31,2553.09 r180 top
R6201 "SB$2F$0402" SB$2F$0402 1071.31,4395.09 r90 bottom
R6202 "SB$2F$0402" SB$2F$0402 1006.45,4396.99 r90 bottom
R6203 "SB$2F$0402" SB$2F$0402 902.45,4329.99 r90 bottom
R6204 "SB$2F$0402" SB$2F$0402 847.95,4352.49 r90 bottom
R6205 "SB$2F$0402" SB$2F$0402 1958.31,4840.09 r0 top
R6206 "SB$2F$0402" SB$2F$0402 1565.31,4887.09 r180 top
R6207 "R0402" R0402 1560.31,4839.09 r270 top
R6209 "SB$2F$0402" SB$2F$0402 1608.31,4850.09 r0 top
R6211 "R0201" R0201 1320.31,4417.09 r180 top
R6212 "R0402" R0402 1386.31,4391.09 r270 bottom
R6307 "SB$2F$0201" SB$2F$0201 164.95,4169.83 r180 top
R6308 "SB$2F$0201" SB$2F$0201 165.95,4118.83 r0 top
R6311 "SB$2F$0402" SB$2F$0402 1618.31,4478.09 r90 bottom
R6313 "SB$2F$0402" SB$2F$0402 1673.31,4459.09 r0 bottom
R6314 "R0402" R0402 1544.31,3858.09 r270 top
R6318 "SB$2F$0201" SB$2F$0201 328.95,4059.83 r90 top
R6350 "R0402" R0402 714.88,4738.78 r90 top
R6351 "R0402" R0402 558.95,4657.99 r90 top
R6352 "R0402" R0402 528.95,4657.99 r90 top
R6501 "R0402" R0402 164.95,1786.83 r90 top
R6504 "R0402" R0402 337.95,1566.83 r90 top
R6507 "R0201" R0201 2041.3,4920.09 r90 bottom
R6508 "R0201" R0201 254.31,4473.09 r90 top
R6509 "R0201" R0201 284.31,4483.09 r180 top
R6510 "R0201" R0201 232.31,4472.09 r90 top
R6601 "SB$2F$0201" SB$2F$0201 2182.95,859.83 r270 bottom
REC6001 "RECEIVE$2F$SMD$2F$NXP" RECEIVE$2F$SMD$2F$NXP 1226.3,4999.09 r270 top
SC9101 "SHIELD_CAN_CLIP$2F$PTV0703B" SHIELD_CAN_CLIP$2F$PTV0703B 1632.95,3957.49 r270 bottom
SC9102 "SHIELD_CAN_CLIP$2F$PTV0703B" SHIELD_CAN_CLIP$2F$PTV0703B 1350.95,4330.49 r0 top
SC9103 "SHIELD_CAN_CLIP$2F$PTV0703B" SHIELD_CAN_CLIP$2F$PTV0703B 1844.49,3333.49 r0 top
SC9104 "SHIELD_CAN_CLIP$2F$PTV0703B" SHIELD_CAN_CLIP$2F$PTV0703B 2310.31,3934.59 r270 bottom
SC9105 "SHIELD_CAN_CLIP$2F$PTV0703B" SHIELD_CAN_CLIP$2F$PTV0703B 1843.47,4222.59 r180 top
SC9106 "SHIELD_CAN_CLIP$2F$PTV0703B" SHIELD_CAN_CLIP$2F$PTV0703B 1630.31,4166.49 r90 top
SC9107 "SHIELD_CAN_CLIP$2F$PTV0703B" SHIELD_CAN_CLIP$2F$PTV0703B 1024.95,2810.09 r0 top
SC9108 "SHIELD_CAN_CLIP$2F$PTV0703B" SHIELD_CAN_CLIP$2F$PTV0703B 1793.95,3333.49 r180 bottom
SC9109 "SHIELD_CAN_CLIP$2F$PTV0703B" SHIELD_CAN_CLIP$2F$PTV0703B 393.31,3800.49 r90 top
SC9110 "SHIELD_CAN_CLIP$2F$PTV0703B" SHIELD_CAN_CLIP$2F$PTV0703B 1630.31,2982.09 r90 top
SC9111 "SHIELD_CAN_CLIP$2F$PTV0703B" SHIELD_CAN_CLIP$2F$PTV0703B 1176.95,4514.49 r270 top
SC9112 "SHIELD_CAN_CLIP$2F$PTV0703B" SHIELD_CAN_CLIP$2F$PTV0703B 1630.31,3311.09 r270 top
SC9113 "SHIELD_CAN_CLIP$2F$PTV0703B" SHIELD_CAN_CLIP$2F$PTV0703B 1632.95,3508.15 r90 bottom
SC9114 "SHIELD_CAN_CLIP$2F$PTV0703B" SHIELD_CAN_CLIP$2F$PTV0703B 2411.15,3500.61 r90 top
SC9115 "SHIELD_CAN_CLIP$2F$PTV0703B" SHIELD_CAN_CLIP$2F$PTV0703B 1916.14,4152.31 r0 bottom
SC9116 "SHIELD_CAN_CLIP$2F$PTV0703B" SHIELD_CAN_CLIP$2F$PTV0703B 1988.95,3741.5 r180 bottom
SC9117 "SHIELD_CAN_CLIP$2F$PTV0703B" SHIELD_CAN_CLIP$2F$PTV0703B 1839.95,2676.96 r0 top
SC9118 "SHIELD_CAN_CLIP$2F$PTV0703B" SHIELD_CAN_CLIP$2F$PTV0703B 393.31,3436.49 r90 top
SC9119 "SHIELD_CAN_CLIP$2F$PTV0703B" SHIELD_CAN_CLIP$2F$PTV0703B 1843.31,3280.56 r0 top
SC9120 "SHIELD_CAN_CLIP$2F$PTV0703B" SHIELD_CAN_CLIP$2F$PTV0703B 1467.31,2810.09 r0 top
SC9121 "SHIELD_CAN_CLIP$2F$PTV0703B" SHIELD_CAN_CLIP$2F$PTV0703B 2113.76,3333.53 r180 bottom
SC9128 "SHIELD_CAN_CLIP$2F$3P$2F$SMD$2F$PTV3121N" SHIELD_CAN_CLIP$2F$3P$2F$SMD$2F$PTV3121N 395.95,1651.49 r0 top
SC9129 "SHIELD_CAN_CLIP$2F$3P$2F$SMD$2F$PTV3121N" SHIELD_CAN_CLIP$2F$3P$2F$SMD$2F$PTV3121N 748.95,1767.49 r90 top
SC9130 "SHIELD_CAN_CLIP$2F$3P$2F$SMD$2F$PTV3121N" SHIELD_CAN_CLIP$2F$3P$2F$SMD$2F$PTV3121N 1679.31,4672.09 r90 top
SC9131 "SHIELD_CAN_CLIP$2F$3P$2F$SMD$2F$PTV3121N" SHIELD_CAN_CLIP$2F$3P$2F$SMD$2F$PTV3121N 748.95,2066.49 r90 top
SC9132 "SHIELD_CAN_CLIP$2F$3P$2F$SMD$2F$PTV3121N" SHIELD_CAN_CLIP$2F$3P$2F$SMD$2F$PTV3121N 1680.95,4103.49 r270 top
SC9133 "SHIELD_CAN_CLIP$2F$3P$2F$SMD$2F$PTV3121N" SHIELD_CAN_CLIP$2F$3P$2F$SMD$2F$PTV3121N 2309.5,3531.01 r90 bottom
SC9134 "SHIELD_CAN_CLIP$2F$3P$2F$SMD$2F$PTV3121N" SHIELD_CAN_CLIP$2F$3P$2F$SMD$2F$PTV3121N 622.95,2183.49 r0 top
SC9135 "SHIELD_CAN_CLIP$2F$3P$2F$SMD$2F$PTV3121N" SHIELD_CAN_CLIP$2F$3P$2F$SMD$2F$PTV3121N 1963.95,4543.49 r180 bottom
SC9136 "SHIELD_CAN_CLIP$2F$3P$2F$SMD$2F$PTV3121N" SHIELD_CAN_CLIP$2F$3P$2F$SMD$2F$PTV3121N 1681.31,3864.09 r270 top
SC9137 "SHIELD_CAN_CLIP$2F$3P$2F$SMD$2F$PTV3121N" SHIELD_CAN_CLIP$2F$3P$2F$SMD$2F$PTV3121N 278.95,2065.49 r90 top
SC9138 "SHIELD_CAN_CLIP$2F$PTV0703B" SHIELD_CAN_CLIP$2F$PTV0703B 1682.95,3116.96 r270 top
SC9139 "SHIELD_CAN_CLIP$2F$PTV0703B" SHIELD_CAN_CLIP$2F$PTV0703B 611.31,4507.09 r270 top
SC9140 "SHIELD_CAN_CLIP$2F$PTV0703B" SHIELD_CAN_CLIP$2F$PTV0703B 393.31,2975.09 r90 top
SC9141 "SHIELD_CAN_CLIP$2F$PTV0703B" SHIELD_CAN_CLIP$2F$PTV0703B 2184.6,3333.07 r180 top
SC9142 "SHIELD_CAN_CLIP$2F$PTV0703B" SHIELD_CAN_CLIP$2F$PTV0703B 772.95,4673.49 r0 top
SC9145 "SHIELD_CAN_CLIP$2F$3P$2F$SMD$2F$PTV3121N" SHIELD_CAN_CLIP$2F$3P$2F$SMD$2F$PTV3121N 2083.31,4301.09 r0 top
SC9146 "SHIELD_CAN_CLIP$2F$3P$2F$SMD$2F$PTV3121N" SHIELD_CAN_CLIP$2F$3P$2F$SMD$2F$PTV3121N 396.95,2183.49 r0 top
SC9147 "SHIELD_CAN_CLIP$2F$3P$2F$SMD$2F$PTV3121N" SHIELD_CAN_CLIP$2F$3P$2F$SMD$2F$PTV3121N 278.95,1772.49 r90 top
SC9148 "SHIELD_CAN_CLIP$2F$3P$2F$SMD$2F$PTV3121N" SHIELD_CAN_CLIP$2F$3P$2F$SMD$2F$PTV3121N 1854.95,4379.47 r270 bottom
SC9149 "SHIELD_CAN_CLIP$2F$3P$2F$SMD$2F$PTV3121N" SHIELD_CAN_CLIP$2F$3P$2F$SMD$2F$PTV3121N 2001.31,2793.56 r90 top
SC9150 "SHIELD_CAN_CLIP$2F$3P$2F$SMD$2F$PTV3121N" SHIELD_CAN_CLIP$2F$3P$2F$SMD$2F$PTV3121N 2202.59,4418.3 r270 top
SC9151 "SHIELD_CAN_CLIP$2F$3P$2F$SMD$2F$PTV3121N" SHIELD_CAN_CLIP$2F$3P$2F$SMD$2F$PTV3121N 2065.17,4379.47 r270 bottom
SC9152 "SHIELD_CAN_CLIP$2F$3P$2F$SMD$2F$PTV3121N" SHIELD_CAN_CLIP$2F$3P$2F$SMD$2F$PTV3121N 1680.77,3539.92 r270 top
SC9153 "SHIELD_CAN_CLIP$2F$PTV0703B" SHIELD_CAN_CLIP$2F$PTV0703B 1843.31,2963.56 r0 top
SC9154 "SHIELD_CAN_CLIP$2F$PTV0703B" SHIELD_CAN_CLIP$2F$PTV0703B 562.31,2810.09 r0 top
SC9155 "SHIELD_CAN_CLIP$2F$PTV0703B" SHIELD_CAN_CLIP$2F$PTV0703B 2123.81,4222.09 r0 top
SC9156 "SHIELD_CAN_CLIP$2F$PTV0703B" SHIELD_CAN_CLIP$2F$PTV0703B 2411.15,3817.09 r90 top
SC9157 "SHIELD_CAN_CLIP$2F$PTV0703B" SHIELD_CAN_CLIP$2F$PTV0703B 393.31,4126.09 r90 top
SC9158 "SHIELD_CAN_CLIP$2F$PTV0703B" SHIELD_CAN_CLIP$2F$PTV0703B 2004.95,3116.96 r90 top
SC9159 "SHIELD_CAN_CLIP$2F$PTV0703B" SHIELD_CAN_CLIP$2F$PTV0703B 1630.31,3800.49 r270 top
SC9161 "SHIELD_CAN_CLIP$2F$3P$2F$SMD$2F$PTV3121N" SHIELD_CAN_CLIP$2F$3P$2F$SMD$2F$PTV3121N 2344.95,4147.49 r315 top
SC9162 "SHIELD_CAN_CLIP$2F$3P$2F$SMD$2F$PTV3121N" SHIELD_CAN_CLIP$2F$3P$2F$SMD$2F$PTV3121N 769.95,4287.49 r180 top
SC9163 "SHIELD_CAN_CLIP$2F$3P$2F$SMD$2F$PTV3121N" SHIELD_CAN_CLIP$2F$3P$2F$SMD$2F$PTV3121N 630.95,1651.49 r0 top
SC9164 "SHIELD_CAN_CLIP$2F$3P$2F$SMD$2F$PTV3121N" SHIELD_CAN_CLIP$2F$3P$2F$SMD$2F$PTV3121N 1680.95,2795.96 r90 top
SC9165 "SHIELD_CAN_CLIP$2F$3P$2F$SMD$2F$PTV3121N" SHIELD_CAN_CLIP$2F$3P$2F$SMD$2F$PTV3121N 1961.95,4203.49 r180 bottom
SC9166 "SHIELD_CAN_CLIP$2F$3P$2F$SMD$2F$PTV3121N" SHIELD_CAN_CLIP$2F$3P$2F$SMD$2F$PTV3121N 1680.82,4420.09 r90 top
SC9167 "SHIELD_CAN_CLIP$2F$3P$2F$SMD$2F$PTV3121N" SHIELD_CAN_CLIP$2F$3P$2F$SMD$2F$PTV3121N 1056.31,4673.49 r0 top
SC9168 "SHIELD_CAN_CLIP$2F$3P$2F$SMD$2F$PTV3121N" SHIELD_CAN_CLIP$2F$3P$2F$SMD$2F$PTV3121N 1800.31,4301.09 r0 top
SC9169 "SHIELD_CAN_CLIP$2F$3P$2F$SMD$2F$PTV3121N" SHIELD_CAN_CLIP$2F$3P$2F$SMD$2F$PTV3121N 2085.23,4787.57 r0 top
SC9170 "SHIELD_CAN_CLIP$2F$3P$2F$SMD$2F$PTV3121N" SHIELD_CAN_CLIP$2F$3P$2F$SMD$2F$PTV3121N 1793.23,4787.59 r0 top
SC9171 "SHIELD_CAN_CLIP$2F$3P$2F$SMD$2F$PTV3121N" SHIELD_CAN_CLIP$2F$3P$2F$SMD$2F$PTV3121N 515.31,4287.49 r0 top
SC9172 "SHIELD_CAN_CLIP$2F$3P$2F$SMD$2F$PTV3121N" SHIELD_CAN_CLIP$2F$3P$2F$SMD$2F$PTV3121N 2202.12,4668.29 r90 top
SC9185 "CABLE_CLIP$2F$3P$2F$SMD$2F$PCV1003" CABLE_CLIP$2F$3P$2F$SMD$2F$PCV1003 2266.08,2851.11 r338 top
SC9186 "CABLE_CLIP$2F$3P$2F$SMD$2F$PCV1003" CABLE_CLIP$2F$3P$2F$SMD$2F$PCV1003 694.08,825.11 r116.79 top
SH1001 "NC$2F$MMD$2F$L1$2F$4MIL" NC$2F$MMD$2F$L1$2F$4MIL 1326.31,4081.09 r0 bottom
SH1002 "NC$2F$MMD$2F$L1$2F$4MIL" NC$2F$MMD$2F$L1$2F$4MIL 1186.31,3971.09 r270 bottom
SH1003 "NC$2F$MMD$2F$L1$2F$4MIL" NC$2F$MMD$2F$L1$2F$4MIL 1397.31,3882.09 r270 bottom
SH1004 "NC$2F$MMD$2F$L1$2F$4MIL" NC$2F$MMD$2F$L1$2F$4MIL 1397.31,3840.09 r90 bottom
SH1005 "NC$2F$MMD$2F$L1$2F$4MIL" NC$2F$MMD$2F$L1$2F$4MIL 1113.95,3755.49 r270 bottom
SH1006 "NC$2F$MMD$2F$L1$2F$4MIL" NC$2F$MMD$2F$L1$2F$4MIL 1148.95,3743.49 r0 bottom
SH2009 "SB$2F$0603" SB$2F$0603 1362.31,3024.09 r90 top
SH2010 "SB$2F$0603" SB$2F$0603 1306.31,2906.09 r90 top
SH2011 "SB$2F$0603" SB$2F$0603 1412.31,3024.09 r90 top
SH2012 "SB$2F$0603" SB$2F$0603 1131.45,3338.49 r270 top
SH2013 "SB$2F$0603" SB$2F$0603 1122.95,2916.49 r90 top
SH2014 "SB$2F$0402" SB$2F$0402 1066.58,2855.15 r180 top
SH4101 "SB$2F$0201" SB$2F$0201 454.95,3993.49 r0 top
SH5001 "SB$2F$0201" SB$2F$0201 852.23,4414.26 r270 top
SH5002 "SB$2F$0201" SB$2F$0201 1138.31,4479.09 r90 top
SH5101 "SB$2F$0402" SB$2F$0402 632.95,1928.49 r270 top
SH5102 "SB$2F$0402" SB$2F$0402 686.95,1893.49 r180 top
SH5103 "NC$2F$MMD$2F$L1$2F$4MIL" NC$2F$MMD$2F$L1$2F$4MIL 329.31,1727.09 r90 top
SH5104 "SB$2F$0402" SB$2F$0402 687.95,1833.49 r180 top
SH5105 "SB$2F$0402" SB$2F$0402 687.95,1803.49 r180 top
SH5106 "NC$2F$MMD$2F$L1$2F$4MIL" NC$2F$MMD$2F$L1$2F$4MIL 687.95,1863.49 r180 top
SH5107 "NC$2F$MMD$2F$L1$2F$4MIL" NC$2F$MMD$2F$L1$2F$4MIL 621.3,1754.09 r180 top
SH5108 "NC$2F$MMD$2F$L1$2F$4MIL" NC$2F$MMD$2F$L1$2F$4MIL 700.31,1721.09 r90 top
SH5109 "SB$2F$0402" SB$2F$0402 596.31,1705.09 r180 top
SH5110 "SB$2F$0402" SB$2F$0402 361.31,1779.09 r0 top
SH5111 "SB$2F$0402" SB$2F$0402 520.96,1989.49 r270 top
SH5112 "NC$2F$MMD$2F$L1$2F$4MIL" NC$2F$MMD$2F$L1$2F$4MIL 550.95,1721.49 r90 top
SH5113 "NC$2F$MMD$2F$L1$2F$4MIL" NC$2F$MMD$2F$L1$2F$4MIL 530.95,1721.49 r90 top
SH5114 "NC$2F$MMD$2F$L1$2F$4MIL" NC$2F$MMD$2F$L1$2F$4MIL 316.31,1859.09 r270 top
SH5115 "NC$2F$MMD$2F$L1$2F$4MIL" NC$2F$MMD$2F$L1$2F$4MIL 463.31,1984.09 r270 top
SH5116 "NC$2F$MMD$2F$L1$2F$4MIL" NC$2F$MMD$2F$L1$2F$4MIL 375.95,1712.49 r90 top
SH5117 "NC$2F$MMD$2F$L1$2F$4MIL" NC$2F$MMD$2F$L1$2F$4MIL 405.95,1712.49 r90 top
SH5118 "NC$2F$MMD$2F$L1$2F$4MIL" NC$2F$MMD$2F$L1$2F$4MIL 435.95,1712.49 r90 top
SH6003 "NC$2F$R" NC$2F$R 1980.31,172.09 r0 top
SH6004 "NC$2F$R" NC$2F$R 664.31,4806.09 r180 top
SH6501 "SB$2F$0402" SB$2F$0402 214.95,1797.83 r180 top
SH6502 "SB$2F$0402" SB$2F$0402 391.31,1547.09 r180 top
SPK6001 "SPEAKER$2F$SMD$2F$2403-260-00071" SPEAKER$2F$SMD$2F$2403-260-00071 1170.95,629.49 r180 bottom
TP2015 "TP$2F$SMD$2F$12MIL" TP$2F$SMD$2F$12MIL 800,2982.5 r90 top
TP2016 "TP$2F$SMD$2F$12MIL" TP$2F$SMD$2F$12MIL 861.31,2976.09 r0 top
TP2029 "TP$2F$SMD$2F$12MIL" TP$2F$SMD$2F$12MIL 2505.31,2797.09 r0 top
TP3601 "TP30MIL" TP30MIL 256.3,250.09 r0 top
TP3602 "TP30MIL" TP30MIL 159.3,251.09 r0 top
TP3603 "TP30MIL" TP30MIL 365.3,250.09 r0 top
TP3701 "TP$2F$SMD$2F$12MIL" TP$2F$SMD$2F$12MIL 1788.3,4557.09 r180 bottom
TP3702 "TP$2F$SMD$2F$12MIL" TP$2F$SMD$2F$12MIL 1817.31,4539.09 r180 bottom
TP3703 "TP$2F$SMD$2F$12MIL" TP$2F$SMD$2F$12MIL 1795.31,4589.09 r180 bottom
TP3704 "TP$2F$SMD$2F$12MIL" TP$2F$SMD$2F$12MIL 1759.31,4493.09 r180 bottom
TP3705 "TP$2F$SMD$2F$12MIL" TP$2F$SMD$2F$12MIL 1781.31,4512.09 r180 bottom
TP3706 "TP$2F$SMD$2F$12MIL" TP$2F$SMD$2F$12MIL 1810.3,4500.09 r90 bottom
TP3707 "TP$2F$SMD$2F$12MIL" TP$2F$SMD$2F$12MIL 1910.31,4694.09 r0 top
TP3708 "TP$2F$SMD$2F$12MIL" TP$2F$SMD$2F$12MIL 1767.31,4367.09 r0 top
TP3709 "TP$2F$SMD$2F$12MIL" TP$2F$SMD$2F$12MIL 1758.3,4575.09 r180 bottom
TP3710 "TP$2F$SMD$2F$12MIL" TP$2F$SMD$2F$12MIL 1812.31,4412.09 r180 bottom
TP3711 "TP$2F$SMD$2F$12MIL" TP$2F$SMD$2F$12MIL 1815.3,4439.09 r180 bottom
TP3712 "TP$2F$SMD$2F$12MIL" TP$2F$SMD$2F$12MIL 1816.3,4387.09 r180 bottom
TP3713 "TP$2F$SMD$2F$12MIL" TP$2F$SMD$2F$12MIL 1817.3,4361.09 r180 bottom
TP3714 "TP$2F$SMD$2F$12MIL" TP$2F$SMD$2F$12MIL 1781.31,4470.09 r180 bottom
TP3715 "TP$2F$SMD$2F$12MIL" TP$2F$SMD$2F$12MIL 1782.3,4425.09 r180 bottom
TP3716 "TP$2F$SMD$2F$12MIL" TP$2F$SMD$2F$12MIL 1751.3,4408.09 r180 bottom
TP3717 "TP$2F$SMD$2F$12MIL" TP$2F$SMD$2F$12MIL 1747.31,4450.09 r180 bottom
TP3718 "TP$2F$SMD$2F$12MIL" TP$2F$SMD$2F$12MIL 2252.31,4489.09 r0 top
TP3719 "TP$2F$SMD$2F$12MIL" TP$2F$SMD$2F$12MIL 2016.31,4352.09 r0 top
TP3720 "TP$2F$SMD$2F$12MIL" TP$2F$SMD$2F$12MIL 1714.31,4746.09 r0 top
TP3801 "TP$2F$SMD$2F$12MIL" TP$2F$SMD$2F$12MIL 2150.31,4465.09 r90 top
TP3802 "TP$2F$SMD$2F$12MIL" TP$2F$SMD$2F$12MIL 2147.31,4687.09 r0 top
TP3901 "TP$2F$SMD$2F$12MIL" TP$2F$SMD$2F$12MIL 1823.95,4227.99 r90 bottom
TP3902 "TP$2F$SMD$2F$12MIL" TP$2F$SMD$2F$12MIL 1969.31,2879.56 r0 top
TP3903 "TP$2F$SMD$2F$12MIL" TP$2F$SMD$2F$12MIL 1823.95,4207.99 r90 bottom
TP3904 "TP$2F$SMD$2F$12MIL" TP$2F$SMD$2F$12MIL 1823.95,4190.49 r90 bottom
TP3905 "TP$2F$SMD$2F$12MIL" TP$2F$SMD$2F$12MIL 1948.95,2878.96 r0 top
TP5101 "TP$2F$SMD$2F$12MIL" TP$2F$SMD$2F$12MIL 570.31,1745.09 r0 top
TP5102 "TP$2F$SMD$2F$12MIL" TP$2F$SMD$2F$12MIL 511.3,1724.09 r0 top
U1001 "MT6735$2F$VFBGA641$2F$P0.4$2F$B0.25$2F$12.6X12.6" MT6735$2F$VFBGA641$2F$P0.4$2F$B0.25$2F$12.6X12.6 1218.95,3905.49 r90 top
U2001 "MT6328$2F$VFBGA206$2F$P0.4$2F$B0.25$2F$6.6X6.6" MT6328$2F$VFBGA206$2F$P0.4$2F$B0.25$2F$6.6X6.6 954.95,3140.83 r270 top
U2106 "SOT-6" SOT-6 543.31,3682.09 r180 bottom
U2116 "2-1L1B$2F$SMD$2F$SSM3K35MFV" 2-1L1B$2F$SMD$2F$SSM3K35MFV 528.31,3352.09 r270 bottom
U2301 "DSBGA9$2F$SMD$2F$P0.5$2F$LM3642" DSBGA9$2F$SMD$2F$P0.5$2F$LM3642 164.95,3561.5 r90 bottom
U2305 "SON6$2F$SMD$2F$P0.65$2F$TPS61161" SON6$2F$SMD$2F$P0.65$2F$TPS61161 407.95,2644.49 r90 top
U2401 "WDFN8$2F$SMD$2F$P0.5$2F$NCP6324" WDFN8$2F$SMD$2F$P0.5$2F$NCP6324 786.54,3534.11 r90 bottom
U2402 "WLCSP6$2F$P0.4$2F$B0.2$2F$FAN53611" WLCSP6$2F$P0.4$2F$B0.2$2F$FAN53611 1446.31,2874.09 r180 top
U3101 "MT6169$2F$VFBGA175$2F$P0.4$2F$B0.25$2F$6.2X5.4" MT6169$2F$VFBGA175$2F$P0.4$2F$B0.25$2F$6.2X5.4 1926.65,3898.59 r270 top
U3102 "TCXO$2F$SMD$2F$2.5X2.0$2F$KT2520F" TCXO$2F$SMD$2F$2.5X2.0$2F$KT2520F 1786.65,4120.59 r180 top
U3203 "SKY77643" SKY77643 1955.65,3525.59 r90 bottom
U3210 "BALUN$2F$SMD$2F$HHM22112A2" BALUN$2F$SMD$2F$HHM22112A2 2065.65,3405.59 r270 top
U3215 "FILTER$2F$SMD$2F$885049" FILTER$2F$SMD$2F$885049 1975.65,3515.59 r0 top
U3216 "FILTER$2F$SMD$2F$LFB212G49CG7D755" FILTER$2F$SMD$2F$LFB212G49CG7D755 2070.65,3400.59 r270 bottom
U3220 "ACPF-7141$2F$SMD" ACPF-7141$2F$SMD 1980.65,3450.59 r90 top
U3301 "DUPLEXER$2F$8P$2F$SMD$2F$SAYEY710MBA0F0A" DUPLEXER$2F$8P$2F$SMD$2F$SAYEY710MBA0F0A 2310.65,3895.59 r270 top
U3302 "RF1628" RF1628 2200.65,3870.59 r90 top
U3305 "SAWFILTER$2F$SMD$2F$SAWFD1G90BH0F0A" SAWFILTER$2F$SMD$2F$SAWFD1G90BH0F0A 2030.65,3630.59 r0 top
U3306 "DUPLEXER$2F$8P$2F$SMD$2F$SAYEY710MBA0F0A" DUPLEXER$2F$8P$2F$SMD$2F$SAYEY710MBA0F0A 2192.65,3940.59 r0 top
U3307 "SKY77910" SKY77910 2250.65,3555.59 r0 top
U3308 "DUPLEXER$2F$8P$2F$SMD$2F$SAYEY710MBA0F0A" DUPLEXER$2F$8P$2F$SMD$2F$SAYEY710MBA0F0A 2085.65,3700.59 r270 top
U3309 "DUPLEXER$2F$8P$2F$SMD$2F$SAYEY710MBA0F0A" DUPLEXER$2F$8P$2F$SMD$2F$SAYEY710MBA0F0A 2255.65,3780.59 r180 top
U3313 "DUPLEXER$2F$8P$2F$SMD$2F$SAYEY710MBA0F0A" DUPLEXER$2F$8P$2F$SMD$2F$SAYEY710MBA0F0A 2155.65,3780.59 r270 top
U3317 "BALUN$2F$SMD$2F$TFSZ06051897-3317A1" BALUN$2F$SMD$2F$TFSZ06051897-3317A1 2160.65,3885.59 r90 top
U3322 "SAWFILTER$2F$SMD$2F$F6QB2G595P2BS" SAWFILTER$2F$SMD$2F$F6QB2G595P2BS 1920.65,3580.59 r90 top
U3323 "BALUN$2F$SMD$2F$TFSZ06052460-3310A2" BALUN$2F$SMD$2F$TFSZ06052460-3310A2 1970.65,3630.59 r0 top
U3401 "RF1628" RF1628 2230.65,4010.59 r180 top
U3402 "SKY13418" SKY13418 2145.81,4013.15 r180 bottom
U3403 "SAWFILTER$2F$SMD$2F$F6QB2G595P2BS" SAWFILTER$2F$SMD$2F$F6QB2G595P2BS 1869.15,4088.59 r90 bottom
U3404 "SAWFILTER$2F$SMD$2F$F6QB2G595P2BS" SAWFILTER$2F$SMD$2F$F6QB2G595P2BS 2229.26,4096.16 r90 bottom
U3406 "SAWFILTER$2F$SMD$2F$F6QB2G595P2BS" SAWFILTER$2F$SMD$2F$F6QB2G595P2BS 1969.15,4088.59 r90 bottom
U3407 "SAWFILTER$2F$SMD$2F$F6QB2G595P2BS" SAWFILTER$2F$SMD$2F$F6QB2G595P2BS 1919.15,4088.59 r90 bottom
U3408 "SAWFILTER$2F$SMD$2F$F6QB2G595P2BS" SAWFILTER$2F$SMD$2F$F6QB2G595P2BS 2175.65,4045.59 r180 top
U3410 "BALUN$2F$SMD$2F$TFSZ06052460-3310A2" BALUN$2F$SMD$2F$TFSZ06052460-3310A2 2180.65,3995.59 r90 top
U3411 "SAWFILTER$2F$SMD$2F$F6QB2G595P2BS" SAWFILTER$2F$SMD$2F$F6QB2G595P2BS 2124.15,4102.59 r0 top
U3412 "SAWFILTER$2F$SMD$2F$F6QB2G595P2BS" SAWFILTER$2F$SMD$2F$F6QB2G595P2BS 2255.15,4155.09 r270 top
U3414 "SAWFILTER$2F$SMD$2F$F6QB2G595P2BS" SAWFILTER$2F$SMD$2F$F6QB2G595P2BS 2021.65,4086.09 r270 bottom
U3601 "RF1141A" RF1141A 256.43,443.38 r180 bottom
U3602 "RF1141A" RF1141A 2156.3,4713.09 r270 bottom
U3603 "SKY13489" SKY13489 182.31,611.09 r270 bottom
U3604 "SKY13489" SKY13489 2013.3,4654.09 r0 bottom
U3701 "MT6158$2F$VFBGA91$2F$P0.4$2F$B0.25$2F$4.2X4.2" MT6158$2F$VFBGA91$2F$P0.4$2F$B0.25$2F$4.2X4.2 1871.31,4503.09 r270 top
U3801 "UQFN20$2F$SMD$2F$P0.4$2F$CXM3599UR" UQFN20$2F$SMD$2F$P0.4$2F$CXM3599UR 2110.3,4586.09 r180 top
U3901 "DSBGA9$2F$P0.4$2F$B0.225$2F$LM3242" DSBGA9$2F$P0.4$2F$B0.225$2F$LM3242 1870.68,2808.94 r270 top
U4102 "FBGA221$2F$P0.5$2F$B0.27$2F$11.5X13$2F$SAMSUNG" FBGA221$2F$P0.5$2F$B0.27$2F$11.5X13$2F$SAMSUNG 720.08,3930.11 r0 top
U5001 "MT6625$2F$SQFN40$2F$SMD$2F$P0.4$2F$5X5" MT6625$2F$SQFN40$2F$SMD$2F$P0.4$2F$5X5 1009.08,4375.11 r270 top
U5002 "TCXO$2F$SMD$2F$2.5X2.0$2F$IT2205BE" TCXO$2F$SMD$2F$2.5X2.0$2F$IT2205BE 707.08,4379.11 r270 top
U5003 "SAW$2F$SMD$2F$1.05X1.35" SAW$2F$SMD$2F$1.05X1.35 696.08,4522.11 r270 top
U5004 "TSLP6$2F$SMD$2F$P0.4$2F$BGA725L6$2F$S" TSLP6$2F$SMD$2F$P0.4$2F$BGA725L6$2F$S 851.08,4512.11 r90 top
U5005 "FILTER$2F$SMD$2F$ACPF-7124" FILTER$2F$SMD$2F$ACPF-7124 1104.08,4607.11 r90 top
U5101 "MT6605$2F$MQFN32$2F$SMD$2F$P0.4$2F$4X4$2F$S" MT6605$2F$MQFN32$2F$SMD$2F$P0.4$2F$4X4$2F$S 491.3,1849.09 r0 top
U6301 "WLCSP8$2F$SMD$2F$P0.4$2F$B0.25$2F$AK09911" WLCSP8$2F$SMD$2F$P0.4$2F$B0.25$2F$AK09911 1286.95,4458.49 r180 top
U6302 "QFN16$2F$SMD$2F$P0.5$2F$ITG-1010" QFN16$2F$SMD$2F$P0.5$2F$ITG-1010 280.95,4168.83 r0 top
U6303 "LGA12$2F$SMD$2F$P0.5$2F$MC3410" LGA12$2F$SMD$2F$P0.5$2F$MC3410 1309.95,4581.49 r0 top
VR2101 "SOD882$2F$SMD$2F$PESD5V0S1BL" SOD882$2F$SMD$2F$PESD5V0S1BL 1053.31,3551.09 r90 bottom
VR2102 "SOD882$2F$SMD$2F$PESD5V0S1BL" SOD882$2F$SMD$2F$PESD5V0S1BL 1166.95,3562.49 r90 bottom
X2001 "CRYS$2F$SMD$2F$3.2X1.5$2F$9H032000XX$2F$TXC" CRYS$2F$SMD$2F$3.2X1.5$2F$9H032000XX$2F$TXC 692.31,3280.09 r90 top
X3701 "TCXO3225" TCXO3225 1825.95,4685.49 r270 top
X5101 "CRYS$2F$SMD$2F$FA-128" CRYS$2F$SMD$2F$FA-128 345.31,1946.09 r90 top

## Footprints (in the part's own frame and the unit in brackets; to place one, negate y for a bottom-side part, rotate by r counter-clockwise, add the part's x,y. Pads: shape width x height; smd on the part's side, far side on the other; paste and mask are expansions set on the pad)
2-1L1B$2F$SMD$2F$SSM3K35MFV [mm]
  rect 0.42x0.6 smd: 1(-0.4,-0.6) 2(0.4,-0.6) 3(0,0.6)
  silkscreen extent -0.9,-1.15 0.65,0.45
ACPF-7141$2F$SMD [mm]
  rect 0.2x0.2 smd: 1(-0.55,0.75)
  rect 0.3x0.3 smd: 2(0.55,-0.75) 3(-0.05,0)
  Top region: -0.4,0.9 -0.7,0.9 -0.7,0.6 -0.5,0.6 -0.4,0.7 -0.4,0.9
  Top region: -0.7,-0.9 -0.7,0.3 -0.4,0.3 -0.2,0.5 -0.2,0.9 0.7,0.9 0.7,-0.3 0.2,-0.3 0.2,-0.9 -0.7,-0.9
  silkscreen extent -1.15,-1.09 0.89,1.35
ANT$2F$2P$2F$SMD$2F$P25$2F$3X3 [mm]
  rect 3x3 smd: 1(-12.5,0) 2(12.5,0)
ANT$2F$2P$2F$SMD$2F$PVT1024 [mm]
  rect 0.5x1.5 smd: 1(0,0)
  rect 2.1x1.5 smd: 2(1.65,0)
  silkscreen extent -0.35,-0.85 3.25,0.85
